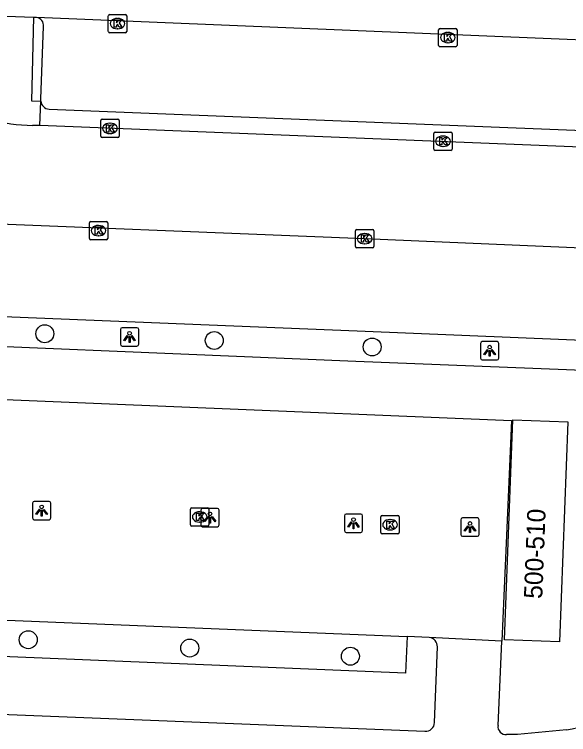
# Model space of a CAD drawing. Extents: x 160891 to 161384, y 386490 to 386907.
# Drawn here: x 160969.9 to 161000.12, y 386737.48 to 386776.73 of the extents above; entities that cross this region are included whole.
import ezdxf

# ---------------------------------------------------------------- set-up
doc = ezdxf.new("R2010")
doc.units = 0
for name, color, linetype in [('IMGEO_Boom', 7, 'Continuous'), ('IMGEO_Fietspad_gesloten', 7, 'Continuous'), ('IMGEO_Haag', 7, 'Continuous'), ('IMGEO_Kolk', 7, 'Continuous'), ('IMGEO_Lichtpunt', 7, 'Continuous'), ('IMGEO_Pand', 7, 'Continuous'), ('IMGEO_Pand_nummerreeks', 7, 'Continuous'), ('IMGEO_Parkeervlak_open', 7, 'Continuous'), ('IMGEO_Rijbaan_lokaal_open', 7, 'Continuous'), ('IMGEO_Verkeerseiland_open', 7, 'Continuous'), ('IMGEO_Voetpad_gesloten', 7, 'Continuous'), ('IMGEO_Voetpad_open', 7, 'Continuous')]:
    doc.layers.add(name, color=color, linetype=linetype)

msp = doc.modelspace()

# ---------------------------------------------------------------- linework, layer by layer
at = {"layer": 'IMGEO_Boom'}
for centre in [(160971.558, 386759.329), (160980.8, 386758.961), (160989.408, 386758.608), (160970.655, 386742.654), (160979.462, 386742.2), (160988.221, 386741.755)]:
    msp.add_circle(centre, 0.489, dxfattribs=at)
at = {"layer": 'IMGEO_Fietspad_gesloten'}
for points in [[(160996.473, 386742.58), (160992.523, 386742.772)], [(160996.272, 386737.982), (160996.473, 386742.58)], [(160992.803, 386738.141), (160992.965, 386742.258)], [(160921.46, 386740.524), (160955.08, 386739.168), (160992.282, 386737.671)], [(161000, 386737.75), (160997.335, 386737.486), (160996.739, 386737.486)]]:
    msp.add_lwpolyline(points, dxfattribs=at)
for centre, radius, start, end in [((160992.474, 386742.283), 0.492, 357.1219, 84.264), ((160996.766, 386756.848), 19.37, 279.6107, 294.7188), ((160992.328, 386738.144), 0.475, 264.4595, 359.6485), ((160996.696, 386737.913), 0.429, 170.7634, 275.7868)]:
    msp.add_arc(centre, radius, start, end, dxfattribs=at)
at = {"layer": 'IMGEO_Haag'}
msp.add_lwpolyline([(160971.292, 386770.67), (160971.342, 386772.013)], dxfattribs=at)
at = {"layer": 'IMGEO_Kolk'}
for p, q in [((160975.022, 386775.806), (160975.022, 386776.658)), ((160975.097, 386776.732), (160975.949, 386776.732)), ((160975.51, 386776.512), (160975.535, 386776.512)), ((160976.023, 386776.658), (160976.023, 386775.806)), ((160975.949, 386775.732), (160975.097, 386775.732)), ((160975.533, 386775.952), (160975.508, 386775.952)), ((160993.033, 386775.045), (160993.033, 386775.897)), ((160993.108, 386775.971), (160993.96, 386775.971)), ((160993.521, 386775.751), (160993.546, 386775.751)), ((160994.034, 386775.897), (160994.034, 386775.045)), ((160993.96, 386774.971), (160993.108, 386774.971)), ((160993.544, 386775.191), (160993.519, 386775.191)), ((160974.684, 386771.019), (160975.536, 386771.019)), ((160974.609, 386770.093), (160974.609, 386770.945)), ((160975.097, 386770.799), (160975.122, 386770.799)), ((160975.61, 386770.945), (160975.61, 386770.093)), ((160975.12, 386770.239), (160975.095, 386770.239)), ((160992.769, 386769.396), (160992.769, 386770.248)), ((160992.844, 386770.322), (160993.696, 386770.322)), ((160993.77, 386770.248), (160993.77, 386769.396)), ((160975.536, 386770.019), (160974.684, 386770.019)), ((160993.257, 386770.102), (160993.282, 386770.102)), ((160993.28, 386769.542), (160993.255, 386769.542)), ((160993.696, 386769.322), (160992.844, 386769.322)), ((160973.987, 386764.523), (160973.987, 386765.375)), ((160974.062, 386765.449), (160974.914, 386765.449)), ((160974.475, 386765.229), (160974.5, 386765.229)), ((160974.988, 386765.375), (160974.988, 386764.523)), ((160974.498, 386764.669), (160974.473, 386764.669)), ((160988.497, 386764.085), (160988.497, 386764.937)), ((160988.572, 386765.011), (160989.424, 386765.011)), ((160988.985, 386764.791), (160989.01, 386764.791)), ((160989.498, 386764.937), (160989.498, 386764.085)), ((160974.914, 386764.449), (160974.062, 386764.449)), ((160989.424, 386764.011), (160988.572, 386764.011)), ((160989.008, 386764.231), (160988.983, 386764.231)), ((160979.506, 386748.919), (160979.506, 386749.771)), ((160979.581, 386749.845), (160980.433, 386749.845)), ((160980.507, 386749.771), (160980.507, 386748.919)), ((160979.994, 386749.625), (160980.019, 386749.625)), ((160989.959, 386749.421), (160990.811, 386749.421)), ((160980.017, 386749.065), (160979.992, 386749.065)), ((160989.884, 386748.495), (160989.884, 386749.347)), ((160990.372, 386749.201), (160990.397, 386749.201)), ((160990.885, 386749.347), (160990.885, 386748.495)), ((160980.433, 386748.845), (160979.581, 386748.845)), ((160990.395, 386748.641), (160990.37, 386748.641)), ((160990.811, 386748.421), (160989.959, 386748.421))]:
    msp.add_line(p, q, dxfattribs=at)
for points in [[(160975.022, 386775.806), (160975.022, 386776.658)], [(160975.097, 386776.732), (160975.949, 386776.732)], [(160976.023, 386776.658), (160976.023, 386775.806)], [(160975.343, 386776.432), (160975.466, 386776.432), (160975.466, 386776.281), (160975.596, 386776.432), (160975.76, 386776.432), (160975.614, 386776.281), (160975.767, 386776.032), (160975.615, 386776.032), (160975.53, 386776.196), (160975.466, 386776.129), (160975.466, 386776.032), (160975.343, 386776.032), (160975.343, 386776.432)], [(160975.949, 386775.732), (160975.097, 386775.732)], [(160993.033, 386775.045), (160993.033, 386775.897)], [(160993.108, 386775.971), (160993.96, 386775.971)], [(160993.354, 386775.671), (160993.477, 386775.671), (160993.477, 386775.52), (160993.607, 386775.671), (160993.771, 386775.671), (160993.625, 386775.52), (160993.778, 386775.271), (160993.626, 386775.271), (160993.541, 386775.435), (160993.477, 386775.368), (160993.477, 386775.271), (160993.354, 386775.271), (160993.354, 386775.671)], [(160994.034, 386775.897), (160994.034, 386775.045)], [(160993.96, 386774.971), (160993.108, 386774.971)], [(160974.684, 386771.019), (160975.536, 386771.019)], [(160974.609, 386770.093), (160974.609, 386770.945)], [(160974.93, 386770.719), (160975.053, 386770.719), (160975.053, 386770.568), (160975.183, 386770.719), (160975.347, 386770.719), (160975.201, 386770.568), (160975.354, 386770.319), (160975.202, 386770.319), (160975.117, 386770.483), (160975.053, 386770.416), (160975.053, 386770.319), (160974.93, 386770.319), (160974.93, 386770.719)], [(160975.61, 386770.945), (160975.61, 386770.093)], [(160992.769, 386769.396), (160992.769, 386770.248)], [(160992.844, 386770.322), (160993.696, 386770.322)], [(160993.77, 386770.248), (160993.77, 386769.396)], [(160975.536, 386770.019), (160974.684, 386770.019)], [(160993.09, 386770.022), (160993.213, 386770.022), (160993.213, 386769.871), (160993.343, 386770.022), (160993.507, 386770.022), (160993.361, 386769.871), (160993.514, 386769.622), (160993.362, 386769.622), (160993.277, 386769.786), (160993.213, 386769.719), (160993.213, 386769.622), (160993.09, 386769.622), (160993.09, 386770.022)], [(160993.696, 386769.322), (160992.844, 386769.322)], [(160973.987, 386764.523), (160973.987, 386765.375)], [(160974.062, 386765.449), (160974.914, 386765.449)], [(160974.308, 386765.149), (160974.431, 386765.149), (160974.431, 386764.998), (160974.561, 386765.149), (160974.725, 386765.149), (160974.579, 386764.998), (160974.732, 386764.749), (160974.58, 386764.749), (160974.495, 386764.913), (160974.431, 386764.846), (160974.431, 386764.749), (160974.308, 386764.749), (160974.308, 386765.149)], [(160974.988, 386765.375), (160974.988, 386764.523)], [(160988.497, 386764.085), (160988.497, 386764.937)], [(160988.572, 386765.011), (160989.424, 386765.011)], [(160988.818, 386764.711), (160988.941, 386764.711), (160988.941, 386764.56), (160989.071, 386764.711), (160989.235, 386764.711), (160989.089, 386764.56), (160989.242, 386764.311), (160989.09, 386764.311), (160989.005, 386764.475), (160988.941, 386764.408), (160988.941, 386764.311), (160988.818, 386764.311), (160988.818, 386764.711)], [(160989.498, 386764.937), (160989.498, 386764.085)], [(160974.914, 386764.449), (160974.062, 386764.449)], [(160989.424, 386764.011), (160988.572, 386764.011)], [(160979.506, 386748.919), (160979.506, 386749.771)], [(160979.581, 386749.845), (160980.433, 386749.845)], [(160980.507, 386749.771), (160980.507, 386748.919)], [(160979.827, 386749.545), (160979.95, 386749.545), (160979.95, 386749.394), (160980.08, 386749.545), (160980.244, 386749.545), (160980.098, 386749.394), (160980.251, 386749.145), (160980.099, 386749.145), (160980.014, 386749.309), (160979.95, 386749.242), (160979.95, 386749.145), (160979.827, 386749.145), (160979.827, 386749.545)], [(160989.959, 386749.421), (160990.811, 386749.421)], [(160989.884, 386748.495), (160989.884, 386749.347)], [(160990.205, 386749.121), (160990.328, 386749.121), (160990.328, 386748.97), (160990.458, 386749.121), (160990.622, 386749.121), (160990.476, 386748.97), (160990.629, 386748.721), (160990.477, 386748.721), (160990.392, 386748.885), (160990.328, 386748.818), (160990.328, 386748.721), (160990.205, 386748.721), (160990.205, 386749.121)], [(160990.885, 386749.347), (160990.885, 386748.495)], [(160980.433, 386748.845), (160979.581, 386748.845)], [(160990.811, 386748.421), (160989.959, 386748.421)]]:
    msp.add_lwpolyline(points, dxfattribs=at)
for centre, start, end in [((160975.099, 386776.656), 91.552, 178.448), ((160975.099, 386776.656), 91.552, 178.448), ((160975.947, 386776.656), 1.552, 88.448), ((160975.947, 386776.656), 1.552, 88.448), ((160975.099, 386775.808), 181.552, 268.448), ((160975.099, 386775.808), 181.552, 268.448), ((160975.947, 386775.808), 271.552, 358.448), ((160975.947, 386775.808), 271.552, 358.448), ((160993.11, 386775.895), 91.552, 178.448), ((160993.11, 386775.895), 91.552, 178.448), ((160993.958, 386775.895), 1.552, 88.448), ((160993.958, 386775.895), 1.552, 88.448), ((160993.11, 386775.047), 181.552, 268.448), ((160993.11, 386775.047), 181.552, 268.448), ((160993.958, 386775.047), 271.552, 358.448), ((160993.958, 386775.047), 271.552, 358.448), ((160974.686, 386770.943), 91.552, 178.448), ((160974.686, 386770.943), 91.552, 178.448), ((160975.534, 386770.943), 1.552, 88.448), ((160975.534, 386770.943), 1.552, 88.448), ((160992.846, 386770.246), 91.552, 178.448), ((160992.846, 386770.246), 91.552, 178.448), ((160993.694, 386770.246), 1.552, 88.448), ((160993.694, 386770.246), 1.552, 88.448), ((160974.686, 386770.095), 181.552, 268.448), ((160974.686, 386770.095), 181.552, 268.448), ((160975.534, 386770.095), 271.552, 358.448), ((160975.534, 386770.095), 271.552, 358.448), ((160992.846, 386769.398), 181.552, 268.448), ((160992.846, 386769.398), 181.552, 268.448), ((160993.694, 386769.398), 271.552, 358.448), ((160993.694, 386769.398), 271.552, 358.448), ((160974.064, 386765.373), 91.552, 178.448), ((160974.064, 386765.373), 91.552, 178.448), ((160974.912, 386765.373), 1.552, 88.448), ((160974.912, 386765.373), 1.552, 88.448), ((160988.574, 386764.935), 91.552, 178.448), ((160988.574, 386764.935), 91.552, 178.448), ((160989.422, 386764.935), 1.552, 88.448), ((160989.422, 386764.935), 1.552, 88.448), ((160974.064, 386764.525), 181.552, 268.448), ((160974.064, 386764.525), 181.552, 268.448), ((160974.912, 386764.525), 271.552, 358.448), ((160974.912, 386764.525), 271.552, 358.448), ((160988.574, 386764.087), 181.552, 268.448), ((160988.574, 386764.087), 181.552, 268.448), ((160989.422, 386764.087), 271.552, 358.448), ((160989.422, 386764.087), 271.552, 358.448), ((160979.583, 386749.769), 91.552, 178.448), ((160979.583, 386749.769), 91.552, 178.448), ((160980.431, 386749.769), 1.552, 88.448), ((160980.431, 386749.769), 1.552, 88.448), ((160989.961, 386749.345), 91.552, 178.448), ((160989.961, 386749.345), 91.552, 178.448), ((160990.809, 386749.345), 1.552, 88.448), ((160990.809, 386749.345), 1.552, 88.448), ((160979.583, 386748.921), 181.552, 268.448), ((160979.583, 386748.921), 181.552, 268.448), ((160980.431, 386748.921), 271.552, 358.448), ((160980.431, 386748.921), 271.552, 358.448), ((160989.961, 386748.497), 181.552, 268.448), ((160989.961, 386748.497), 181.552, 268.448), ((160990.809, 386748.497), 271.552, 358.448), ((160990.809, 386748.497), 271.552, 358.448)]:
    msp.add_arc(centre, 0.0765, start, end, dxfattribs=at)
for centre, major_axis, ratio, start_param, end_param in [((160975.509, 386776.232), (-0.387, 0.002), 0.722429, 4.712389, 7.853982), ((160975.534, 386776.232), (-0.39, 0.002), 0.717154, 1.570796, 4.712389), ((160993.52, 386775.471), (-0.387, 0.002), 0.722429, 4.712389, 7.853982), ((160993.545, 386775.471), (-0.39, 0.002), 0.717154, 1.570796, 4.712389), ((160975.096, 386770.519), (-0.387, 0.002), 0.722429, 4.712389, 7.853982), ((160975.121, 386770.519), (-0.39, 0.002), 0.717154, 1.570796, 4.712389), ((160993.256, 386769.822), (-0.387, 0.002), 0.722429, 4.712389, 7.853982), ((160993.281, 386769.822), (-0.39, 0.002), 0.717154, 1.570796, 4.712389), ((160974.474, 386764.949), (-0.387, 0.002), 0.722429, 4.712389, 7.853982), ((160974.499, 386764.949), (-0.39, 0.002), 0.717154, 1.570796, 4.712389), ((160988.984, 386764.511), (-0.387, 0.002), 0.722429, 4.712389, 7.853982), ((160989.009, 386764.511), (-0.39, 0.002), 0.717154, 1.570796, 4.712389), ((160979.993, 386749.345), (-0.387, 0.002), 0.722429, 4.712389, 7.853982), ((160980.018, 386749.345), (-0.39, 0.002), 0.717154, 1.570796, 4.712389), ((160990.371, 386748.921), (-0.387, 0.002), 0.722429, 4.712389, 7.853982), ((160990.396, 386748.921), (-0.39, 0.002), 0.717154, 1.570796, 4.712389)]:
    msp.add_ellipse(centre, major_axis=major_axis, ratio=ratio, start_param=start_param, end_param=end_param, dxfattribs=at)
at = {"layer": 'IMGEO_Lichtpunt'}
for p, q in [((160976.585, 386759.657), (160975.777, 386759.657)), ((160976.585, 386759.657), (160975.777, 386759.657)), ((160975.683, 386759.562), (160975.683, 386758.755)), ((160975.683, 386759.562), (160975.683, 386758.755)), ((160976.679, 386758.755), (160976.679, 386759.562)), ((160976.679, 386758.755), (160976.679, 386759.562)), ((160995.316, 386758.806), (160995.316, 386757.999)), ((160995.316, 386758.806), (160995.316, 386757.999)), ((160996.218, 386758.901), (160995.41, 386758.901)), ((160996.218, 386758.901), (160995.41, 386758.901)), ((160996.312, 386757.999), (160996.312, 386758.806)), ((160996.312, 386757.999), (160996.312, 386758.806)), ((160975.777, 386758.661), (160976.585, 386758.661)), ((160975.777, 386758.661), (160976.585, 386758.661)), ((160995.41, 386757.905), (160996.218, 386757.905)), ((160995.41, 386757.905), (160996.218, 386757.905)), ((160971.79, 386750.192), (160970.982, 386750.192)), ((160971.79, 386750.192), (160970.982, 386750.192)), ((160970.888, 386750.097), (160970.888, 386749.29)), ((160970.888, 386750.097), (160970.888, 386749.29)), ((160971.884, 386749.29), (160971.884, 386750.097)), ((160971.884, 386749.29), (160971.884, 386750.097)), ((160980.969, 386749.809), (160980.161, 386749.809)), ((160980.969, 386749.809), (160980.161, 386749.809)), ((160980.067, 386749.714), (160980.067, 386748.907)), ((160980.067, 386749.714), (160980.067, 386748.907)), ((160981.063, 386748.907), (160981.063, 386749.714)), ((160981.063, 386748.907), (160981.063, 386749.714)), ((160987.893, 386749.406), (160987.893, 386748.599)), ((160987.893, 386749.406), (160987.893, 386748.599)), ((160988.795, 386749.501), (160987.987, 386749.501)), ((160988.795, 386749.501), (160987.987, 386749.501)), ((160988.889, 386748.599), (160988.889, 386749.406)), ((160988.889, 386748.599), (160988.889, 386749.406)), ((160970.982, 386749.196), (160971.79, 386749.196)), ((160970.982, 386749.196), (160971.79, 386749.196)), ((160994.242, 386749.196), (160994.242, 386748.389)), ((160994.242, 386749.196), (160994.242, 386748.389)), ((160995.144, 386749.291), (160994.336, 386749.291)), ((160995.144, 386749.291), (160994.336, 386749.291)), ((160995.238, 386748.389), (160995.238, 386749.196)), ((160995.238, 386748.389), (160995.238, 386749.196)), ((160980.161, 386748.813), (160980.969, 386748.813)), ((160980.161, 386748.813), (160980.969, 386748.813)), ((160987.987, 386748.505), (160988.795, 386748.505)), ((160987.987, 386748.505), (160988.795, 386748.505)), ((160994.336, 386748.295), (160995.144, 386748.295)), ((160994.336, 386748.295), (160995.144, 386748.295))]:
    msp.add_line(p, q, dxfattribs=at)
for points in [[(160976.057, 386759.226), (160976.096, 386759.198), (160975.908, 386758.936), (160975.87, 386758.963), (160976.057, 386759.226)], [(160976.159, 386759.178), (160976.206, 386759.178), (160976.206, 386758.856), (160976.159, 386758.856), (160976.159, 386759.178)], [(160976.269, 386759.198), (160976.307, 386759.225), (160976.494, 386758.963), (160976.455, 386758.935), (160976.269, 386759.198)], [(160995.69, 386758.47), (160995.729, 386758.442), (160995.541, 386758.18), (160995.503, 386758.207), (160995.69, 386758.47)], [(160995.792, 386758.422), (160995.839, 386758.422), (160995.839, 386758.1), (160995.792, 386758.1), (160995.792, 386758.422)], [(160995.902, 386758.442), (160995.94, 386758.469), (160996.127, 386758.207), (160996.088, 386758.179), (160995.902, 386758.442)], [(160971.262, 386749.761), (160971.301, 386749.733), (160971.113, 386749.471), (160971.075, 386749.498), (160971.262, 386749.761)], [(160971.474, 386749.733), (160971.512, 386749.76), (160971.699, 386749.498), (160971.66, 386749.47), (160971.474, 386749.733)], [(160971.364, 386749.713), (160971.411, 386749.713), (160971.411, 386749.391), (160971.364, 386749.391), (160971.364, 386749.713)], [(160980.441, 386749.378), (160980.48, 386749.35), (160980.292, 386749.088), (160980.254, 386749.115), (160980.441, 386749.378)], [(160980.653, 386749.35), (160980.691, 386749.377), (160980.878, 386749.115), (160980.839, 386749.087), (160980.653, 386749.35)], [(160980.543, 386749.33), (160980.59, 386749.33), (160980.59, 386749.008), (160980.543, 386749.008), (160980.543, 386749.33)], [(160988.267, 386749.07), (160988.306, 386749.042), (160988.118, 386748.78), (160988.08, 386748.807), (160988.267, 386749.07)], [(160988.369, 386749.022), (160988.416, 386749.022), (160988.416, 386748.7), (160988.369, 386748.7), (160988.369, 386749.022)], [(160988.479, 386749.042), (160988.517, 386749.069), (160988.704, 386748.807), (160988.665, 386748.779), (160988.479, 386749.042)], [(160994.616, 386748.86), (160994.655, 386748.832), (160994.467, 386748.57), (160994.429, 386748.597), (160994.616, 386748.86)], [(160994.718, 386748.812), (160994.765, 386748.812), (160994.765, 386748.49), (160994.718, 386748.49), (160994.718, 386748.812)], [(160994.828, 386748.832), (160994.866, 386748.859), (160995.053, 386748.597), (160995.014, 386748.569), (160994.828, 386748.832)]]:
    msp.add_lwpolyline(points, dxfattribs=at)
for centre in [(160976.182, 386759.36), (160995.815, 386758.604), (160971.387, 386749.895), (160980.566, 386749.512), (160988.392, 386749.204), (160994.741, 386748.994)]:
    msp.add_circle(centre, 0.0994, dxfattribs=at)
for centre, start, end in [((160975.777, 386759.562), 90, 180), ((160975.777, 386759.562), 90, 180), ((160976.585, 386759.562), 0, 90), ((160976.585, 386759.562), 0, 90), ((160995.41, 386758.806), 90, 180), ((160995.41, 386758.806), 90, 180), ((160996.218, 386758.806), 0, 90), ((160996.218, 386758.806), 0, 90), ((160975.777, 386758.755), 180, 270), ((160975.777, 386758.755), 180, 270), ((160976.585, 386758.755), 270, 0), ((160976.585, 386758.755), 270, 360), ((160995.41, 386757.999), 180, 270), ((160995.41, 386757.999), 180, 270), ((160996.218, 386757.999), 270, 0), ((160996.218, 386757.999), 270, 360), ((160970.982, 386750.097), 90, 180), ((160970.982, 386750.097), 90, 180), ((160971.79, 386750.097), 0, 90), ((160971.79, 386750.097), 0, 90), ((160980.161, 386749.714), 90, 180), ((160980.161, 386749.714), 90, 180), ((160980.969, 386749.714), 0, 90), ((160980.969, 386749.714), 0, 90), ((160987.987, 386749.406), 90, 180), ((160987.987, 386749.406), 90, 180), ((160988.795, 386749.406), 0, 90), ((160988.795, 386749.406), 0, 90), ((160970.982, 386749.29), 180, 270), ((160970.982, 386749.29), 180, 270), ((160971.79, 386749.29), 270, 0), ((160971.79, 386749.29), 270, 360), ((160994.336, 386749.196), 90, 180), ((160994.336, 386749.196), 90, 180), ((160995.144, 386749.196), 0, 90), ((160995.144, 386749.196), 0, 90), ((160980.161, 386748.907), 180, 270), ((160980.161, 386748.907), 180, 270), ((160980.969, 386748.907), 270, 0), ((160980.969, 386748.907), 270, 360), ((160987.987, 386748.599), 180, 270), ((160987.987, 386748.599), 180, 270), ((160988.795, 386748.599), 270, 0), ((160988.795, 386748.599), 270, 360), ((160994.336, 386748.389), 180, 270), ((160994.336, 386748.389), 180, 270), ((160995.144, 386748.389), 270, 0), ((160995.144, 386748.389), 270, 360)]:
    msp.add_arc(centre, 0.0946, start, end, dxfattribs=at)
at = {"layer": 'IMGEO_Pand'}
msp.add_lwpolyline([(160999.617, 386742.535), (160996.619, 386742.652), (160997.085, 386754.644), (161000.083, 386754.528), (160999.617, 386742.535)], dxfattribs=at)
at = {"layer": 'IMGEO_Parkeervlak_open'}
for points in [[(160971.342, 386772.013), (160971.346, 386772.126), (160971.493, 386776.069)], [(160971.789, 386771.566), (161040.477, 386768.819)], [(160965.706, 386760.42), (160988.591, 386759.479), (161000, 386759.013), (161018.946, 386758.238)], [(160960.156, 386756.131), (160959.912, 386750), (160959.678, 386744.125), (160991.315, 386742.829)]]:
    msp.add_lwpolyline(points, dxfattribs=at)
for centre, radius, start, end in [((160971.017, 386776.105), 0.477, 355.6324, 78.3978), ((160971.827, 386772.051), 0.486, 184.479, 265.521)]:
    msp.add_arc(centre, radius, start, end, dxfattribs=at)
at = {"layer": 'IMGEO_Rijbaan_lokaal_open'}
for points in [[(160966.998, 386776.719), (160970.942, 386776.579)], [(160970.942, 386776.579), (160971.113, 386776.573)], [(160971.113, 386776.573), (161029.864, 386774.147), (161041.138, 386773.741)], [(160971.292, 386770.67), (160970.889, 386770.686)], [(161040.927, 386767.887), (161024.832, 386768.53), (160971.292, 386770.67)], [(160964.56, 386765.508), (160988.998, 386764.511), (161000, 386764.044), (161002.969, 386763.918), (161017.378, 386763.331), (161020.116, 386763.266)]]:
    msp.add_lwpolyline(points, dxfattribs=at)
msp.add_arc((160970.967, 386779.441), 8.755, 238.4981, 269.49, dxfattribs=at)
at = {"layer": 'IMGEO_Verkeerseiland_open'}
msp.add_lwpolyline([(160970.942, 386776.579), (160970.824, 386772.024), (160971.342, 386772.013)], dxfattribs=at)
at = {"layer": 'IMGEO_Voetpad_gesloten'}
for points in [[(160991.315, 386742.829), (160991.231, 386740.83), (160963.905, 386741.957), (160958.336, 386742.153)], [(160992.523, 386742.772), (160991.315, 386742.829)]]:
    msp.add_lwpolyline(points, dxfattribs=at)
at = {"layer": 'IMGEO_Voetpad_open'}
for points in [[(161024.679, 386761.943), (161024.466, 386756.364), (161000, 386757.358), (160988.523, 386757.824), (160959.002, 386759.048)], [(160960.156, 386756.131), (160996.998, 386754.61), (160996.797, 386750), (160996.742, 386748.751), (160996.473, 386742.58)]]:
    msp.add_lwpolyline(points, dxfattribs=at)

# ---------------------------------------------------------------- texts
at = {"layer": 'IMGEO_Pand_nummerreeks'}
msp.add_text('500-510', height=1, rotation=87.773, dxfattribs=at).set_placement((160998.68, 386744.87))

doc.saveas('drawing.dxf')
